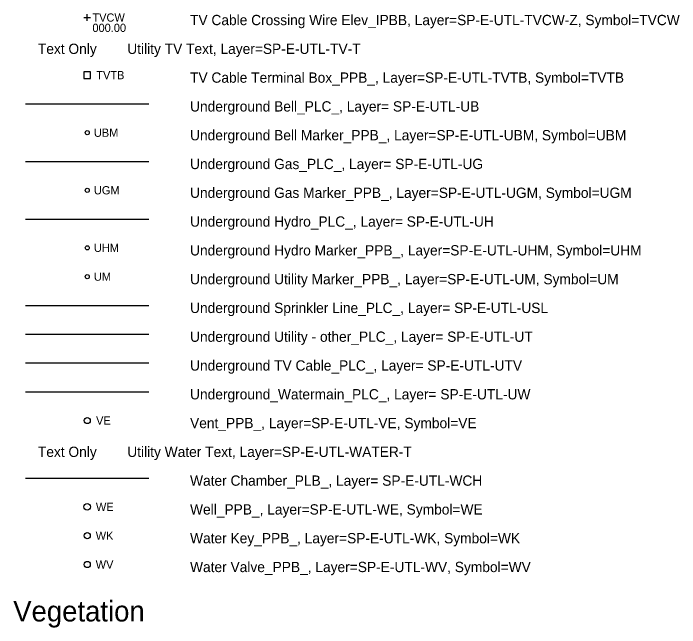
# Model space of a CAD drawing. Extents: x 500528 to 502626, y 4210261 to 4212624.
# Drawn here: x 500883.6 to 501045.6, y 4210553.2 to 4210702.6 of the extents above; entities that cross this region are included whole.
import ezdxf

# ---------------------------------------------------------------- set-up
doc = ezdxf.new("R2010")
doc.units = 0
for name, color, linetype in [('Default', 7, 'Continuous'), ('SP-E-UTL-BELL-T', 7, 'Continuous'), ('SP-E-UTL-GAS-T', 7, 'Continuous'), ('SP-E-UTL-HYDRO-T', 7, 'Continuous'), ('SP-E-UTL-T', 7, 'Continuous'), ('SP-E-UTL-TV-T', 7, 'Continuous'), ('SP-E-UTL-TVCW-Z', 7, 'Continuous'), ('SP-E-UTL-TVTB', 7, 'Continuous'), ('SP-E-UTL-UB', 7, 'Continuous'), ('SP-E-UTL-UBM', 7, 'Continuous'), ('SP-E-UTL-UG', 7, 'Continuous'), ('SP-E-UTL-UGM', 7, 'Continuous'), ('SP-E-UTL-UH', 7, 'Continuous'), ('SP-E-UTL-UHM', 7, 'Continuous'), ('SP-E-UTL-UM', 7, 'Continuous'), ('SP-E-UTL-USL', 7, 'Continuous'), ('SP-E-UTL-UT', 7, 'Continuous'), ('SP-E-UTL-UTV', 7, 'Continuous'), ('SP-E-UTL-UW', 7, 'Continuous'), ('SP-E-UTL-VE', 7, 'Continuous'), ('SP-E-UTL-WATER-T', 7, 'Continuous'), ('SP-E-UTL-WCH', 7, 'Continuous'), ('SP-E-UTL-WE', 7, 'Continuous'), ('SP-E-UTL-WK', 7, 'Continuous'), ('SP-E-UTL-WV', 7, 'Continuous')]:
    doc.layers.add(name, color=color, linetype=linetype)

# ---------------------------------------------------------------- blocks, each defined once
blk = doc.blocks.new('TVCW')
at = {"layer": 'SP-E-UTL-TVCW-Z'}
for points in [[(-0.08, 0), (0.08, 0)], [(0, -0.08), (0, 0.08)]]:
    blk.add_lwpolyline(points, dxfattribs=at)
at = {"layer": 'SP-E-UTL-TV-T'}
for s, p in [('TVCW', (0.126, -0.1)), ('000.00', (0.126, -0.35))]:
    blk.add_text(s, height=0.2, dxfattribs=at).set_placement(p)
blk = doc.blocks.new('TVTB')
at = {"layer": 'SP-E-UTL-TVTB'}
blk.add_lwpolyline([(-0.08, 0.08), (-0.08, -0.08), (0.08, -0.08), (0.08, 0.08), (-0.08, 0.08)], dxfattribs=at)
at = {"layer": 'SP-E-UTL-TV-T'}
blk.add_text('TVTB', height=0.2, dxfattribs=at).set_placement((0.22, -0.1))
blk = doc.blocks.new('UBM')
at = {"layer": 'SP-E-UTL-UBM'}
blk.add_lwpolyline([(0, 0), (0, 0)], dxfattribs=at)
blk.add_circle((0, 0), 0.05, dxfattribs=at)
at = {"layer": 'SP-E-UTL-BELL-T'}
blk.add_text('UBM', height=0.2, dxfattribs=at).set_placement((0.162, -0.1))
blk = doc.blocks.new('UGM')
at = {"layer": 'SP-E-UTL-UGM'}
blk.add_lwpolyline([(0, 0), (0, 0)], dxfattribs=at)
blk.add_circle((0, 0), 0.05, dxfattribs=at)
at = {"layer": 'SP-E-UTL-GAS-T'}
blk.add_text('UGM', height=0.2, dxfattribs=at).set_placement((0.162, -0.1))
blk = doc.blocks.new('UHM')
at = {"layer": 'SP-E-UTL-UHM'}
blk.add_lwpolyline([(0, 0), (0, 0)], dxfattribs=at)
blk.add_circle((0, 0), 0.05, dxfattribs=at)
at = {"layer": 'SP-E-UTL-HYDRO-T'}
blk.add_text('UHM', height=0.2, dxfattribs=at).set_placement((0.162, -0.1))
blk = doc.blocks.new('UM')
at = {"layer": 'SP-E-UTL-UM'}
blk.add_lwpolyline([(0, 0), (0, 0)], dxfattribs=at)
blk.add_circle((0, 0), 0.05, dxfattribs=at)
at = {"layer": 'SP-E-UTL-T'}
blk.add_text('UM', height=0.2, dxfattribs=at).set_placement((0.162, -0.1))
blk = doc.blocks.new('VE')
at = {"layer": 'SP-E-UTL-VE'}
blk.add_lwpolyline([(0, 0), (0, 0)], dxfattribs=at)
blk.add_circle((0, 0), 0.075, dxfattribs=at)
at = {"layer": 'SP-E-UTL-T'}
blk.add_text('VE', height=0.2, dxfattribs=at).set_placement((0.215, -0.1))
blk = doc.blocks.new('WE')
at = {"layer": 'SP-E-UTL-WE'}
blk.add_lwpolyline([(0, 0), (0, 0)], dxfattribs=at)
blk.add_circle((0, 0), 0.08, dxfattribs=at)
at = {"layer": 'SP-E-UTL-T'}
blk.add_text('WE', height=0.2, dxfattribs=at).set_placement((0.211, -0.1))
blk = doc.blocks.new('WK')
at = {"layer": 'SP-E-UTL-WK'}
blk.add_lwpolyline([(0, 0), (0, 0)], dxfattribs=at)
blk.add_circle((0, 0), 0.075, dxfattribs=at)
at = {"layer": 'SP-E-UTL-WATER-T'}
blk.add_text('WK', height=0.2, dxfattribs=at).set_placement((0.206, -0.1))
blk = doc.blocks.new('WV')
at = {"layer": 'SP-E-UTL-WV'}
blk.add_lwpolyline([(0, 0), (0, 0)], dxfattribs=at)
blk.add_circle((0, 0), 0.075, dxfattribs=at)
at = {"layer": 'SP-E-UTL-WATER-T'}
blk.add_text('WV', height=0.2, dxfattribs=at).set_placement((0.206, -0.1))

msp = doc.modelspace()

# ---------------------------------------------------------------- linework, layer by layer
at = {"layer": 'SP-E-UTL-UB'}
msp.add_line((500886.55, 4210680.59), (500916.55, 4210680.59), dxfattribs=at)
at = {"layer": 'SP-E-UTL-UG'}
msp.add_line((500886.55, 4210666.59), (500916.55, 4210666.59), dxfattribs=at)
at = {"layer": 'SP-E-UTL-UH'}
msp.add_line((500886.55, 4210652.59), (500916.55, 4210652.59), dxfattribs=at)
at = {"layer": 'SP-E-UTL-USL'}
msp.add_line((500886.55, 4210631.59), (500916.55, 4210631.59), dxfattribs=at)
at = {"layer": 'SP-E-UTL-UT'}
msp.add_line((500886.55, 4210624.59), (500916.55, 4210624.59), dxfattribs=at)
at = {"layer": 'SP-E-UTL-UTV'}
msp.add_line((500886.55, 4210617.59), (500916.55, 4210617.59), dxfattribs=at)
at = {"layer": 'SP-E-UTL-UW'}
msp.add_line((500886.55, 4210610.59), (500916.55, 4210610.59), dxfattribs=at)
at = {"layer": 'SP-E-UTL-WCH'}
msp.add_line((500886.55, 4210589.59), (500916.55, 4210589.59), dxfattribs=at)

# ---------------------------------------------------------------- block references
at = {"layer": 'SP-E-UTL-TVCW-Z', "xscale": 10, "yscale": 10}
msp.add_blockref('TVCW', (500901.55, 4210701.59), dxfattribs=at)
at = {"layer": 'SP-E-UTL-TVTB', "xscale": 10, "yscale": 10}
msp.add_blockref('TVTB', (500901.55, 4210687.59), dxfattribs=at)
at = {"layer": 'SP-E-UTL-UBM', "xscale": 10, "yscale": 10}
msp.add_blockref('UBM', (500901.55, 4210673.59), dxfattribs=at)
at = {"layer": 'SP-E-UTL-UGM', "xscale": 10, "yscale": 10}
msp.add_blockref('UGM', (500901.55, 4210659.59), dxfattribs=at)
at = {"layer": 'SP-E-UTL-UHM', "xscale": 10, "yscale": 10}
msp.add_blockref('UHM', (500901.55, 4210645.59), dxfattribs=at)
at = {"layer": 'SP-E-UTL-UM', "xscale": 10, "yscale": 10}
msp.add_blockref('UM', (500901.55, 4210638.59), dxfattribs=at)
at = {"layer": 'SP-E-UTL-VE', "xscale": 10, "yscale": 10}
msp.add_blockref('VE', (500901.55, 4210603.59), dxfattribs=at)
at = {"layer": 'SP-E-UTL-WE', "xscale": 10, "yscale": 10}
msp.add_blockref('WE', (500901.55, 4210582.59), dxfattribs=at)
at = {"layer": 'SP-E-UTL-WK', "xscale": 10, "yscale": 10}
msp.add_blockref('WK', (500901.55, 4210575.59), dxfattribs=at)
at = {"layer": 'SP-E-UTL-WV', "xscale": 10, "yscale": 10}
msp.add_blockref('WV', (500901.55, 4210568.59), dxfattribs=at)

# ---------------------------------------------------------------- texts
at = {"layer": 'Default'}
msp.add_text('Vegetation ', height=5, dxfattribs=at).set_placement((500883.55, 4210554.74))
at = {"layer": 'SP-E-UTL-TV-T'}
msp.add_text('Text Only        Utility TV Text, Layer=SP-E-UTL-TV-T', height=2.5, dxfattribs=at).set_placement((500889.55, 4210692.74))
at = {"layer": 'SP-E-UTL-TVCW-Z'}
msp.add_text('TV Cable Crossing Wire Elev_IPBB, Layer=SP-E-UTL-TVCW-Z, Symbol=TVCW ', height=2.5, dxfattribs=at).set_placement((500926.55, 4210699.74))
at = {"layer": 'SP-E-UTL-TVTB'}
msp.add_text('TV Cable Terminal Box_PPB_, Layer=SP-E-UTL-TVTB, Symbol=TVTB ', height=2.5, dxfattribs=at).set_placement((500926.55, 4210685.74))
at = {"layer": 'SP-E-UTL-UB'}
msp.add_text('Underground Bell_PLC_, Layer= SP-E-UTL-UB ', height=2.5, dxfattribs=at).set_placement((500926.55, 4210678.74))
at = {"layer": 'SP-E-UTL-UBM'}
msp.add_text('Underground Bell Marker_PPB_, Layer=SP-E-UTL-UBM, Symbol=UBM ', height=2.5, dxfattribs=at).set_placement((500926.55, 4210671.74))
at = {"layer": 'SP-E-UTL-UG'}
msp.add_text('Underground Gas_PLC_, Layer= SP-E-UTL-UG ', height=2.5, dxfattribs=at).set_placement((500926.55, 4210664.74))
at = {"layer": 'SP-E-UTL-UGM'}
msp.add_text('Underground Gas Marker_PPB_, Layer=SP-E-UTL-UGM, Symbol=UGM ', height=2.5, dxfattribs=at).set_placement((500926.55, 4210657.74))
at = {"layer": 'SP-E-UTL-UH'}
msp.add_text('Underground Hydro_PLC_, Layer= SP-E-UTL-UH ', height=2.5, dxfattribs=at).set_placement((500926.55, 4210650.74))
at = {"layer": 'SP-E-UTL-UHM'}
msp.add_text('Underground Hydro Marker_PPB_, Layer=SP-E-UTL-UHM, Symbol=UHM ', height=2.5, dxfattribs=at).set_placement((500926.55, 4210643.74))
at = {"layer": 'SP-E-UTL-UM'}
msp.add_text('Underground Utility Marker_PPB_, Layer=SP-E-UTL-UM, Symbol=UM ', height=2.5, dxfattribs=at).set_placement((500926.55, 4210636.74))
at = {"layer": 'SP-E-UTL-USL'}
msp.add_text('Underground Sprinkler Line_PLC_, Layer= SP-E-UTL-USL ', height=2.5, dxfattribs=at).set_placement((500926.55, 4210629.74))
at = {"layer": 'SP-E-UTL-UT'}
msp.add_text('Underground Utility - other_PLC_, Layer= SP-E-UTL-UT ', height=2.5, dxfattribs=at).set_placement((500926.55, 4210622.74))
at = {"layer": 'SP-E-UTL-UTV'}
msp.add_text('Underground TV Cable_PLC_, Layer= SP-E-UTL-UTV ', height=2.5, dxfattribs=at).set_placement((500926.55, 4210615.74))
at = {"layer": 'SP-E-UTL-UW'}
msp.add_text('Underground_Watermain_PLC_, Layer= SP-E-UTL-UW ', height=2.5, dxfattribs=at).set_placement((500926.55, 4210608.74))
at = {"layer": 'SP-E-UTL-VE'}
msp.add_text('Vent_PPB_, Layer=SP-E-UTL-VE, Symbol=VE ', height=2.5, dxfattribs=at).set_placement((500926.55, 4210601.74))
at = {"layer": 'SP-E-UTL-WATER-T'}
msp.add_text('Text Only        Utility Water Text, Layer=SP-E-UTL-WATER-T', height=2.5, dxfattribs=at).set_placement((500889.55, 4210594.74))
at = {"layer": 'SP-E-UTL-WCH'}
msp.add_text('Water Chamber_PLB_, Layer= SP-E-UTL-WCH ', height=2.5, dxfattribs=at).set_placement((500926.55, 4210587.74))
at = {"layer": 'SP-E-UTL-WE'}
msp.add_text('Well_PPB_, Layer=SP-E-UTL-WE, Symbol=WE ', height=2.5, dxfattribs=at).set_placement((500926.55, 4210580.74))
at = {"layer": 'SP-E-UTL-WK'}
msp.add_text('Water Key_PPB_, Layer=SP-E-UTL-WK, Symbol=WK ', height=2.5, dxfattribs=at).set_placement((500926.55, 4210573.74))
at = {"layer": 'SP-E-UTL-WV'}
msp.add_text('Water Valve_PPB_, Layer=SP-E-UTL-WV, Symbol=WV ', height=2.5, dxfattribs=at).set_placement((500926.55, 4210566.74))

doc.saveas('drawing.dxf')
